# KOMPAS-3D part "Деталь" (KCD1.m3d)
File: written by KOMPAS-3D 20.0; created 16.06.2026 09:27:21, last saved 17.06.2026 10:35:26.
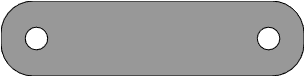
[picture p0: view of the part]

Document properties: Полное имя файла: D:\RicWork\Project-EPS32\box_compas\KCD1.m3d

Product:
- Part/product: Деталь
    Масса: 0.0193926
  - Body: Тело 1
      Масса: 0.0139491
  - Body: Тело 3
      Масса: 0.00544352

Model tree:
1. Эскиз:1
2. Элемент выдавливания:1
     Расстояние 1 = 2
3. Скругление:1  (with: Элемент выдавливания:1)
     Радиус = 5
4. Эскиз:2  (with: Элемент выдавливания:1, Скругление:1)
5. Элемент выдавливания:2
     Расстояние 2 = 2
6. Массив по сетке:1  (with: Элемент выдавливания:2, Эскиз:2)  (2 pattern instances)
     Шаг 1 = 36; Угол раствора = 90
7. Эскиз:3  (with: Элемент выдавливания:1)
8. Элемент выдавливания:3
     Расстояние 1 = 9.2
9. Скругление:2  (with: Элемент выдавливания:3)
     Радиус = 5
10. Эскиз:4  (with: Элемент выдавливания:3)
11. Элемент выдавливания:7
     Расстояние 2 = 10
12. Эскиз:5  (with: Элемент выдавливания:3)
13. Элемент выдавливания:9
     Расстояние 1 = 8.3
14. Эскиз:6  (with: Элемент выдавливания:9)
15. Элемент выдавливания:10
     Расстояние 2 = 9.1
16. Скругление:3  (with: Элемент выдавливания:10)
     Радиус = 1
17. Скругление:4  (with: Элемент выдавливания:9)
     Полуось 1 = 5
